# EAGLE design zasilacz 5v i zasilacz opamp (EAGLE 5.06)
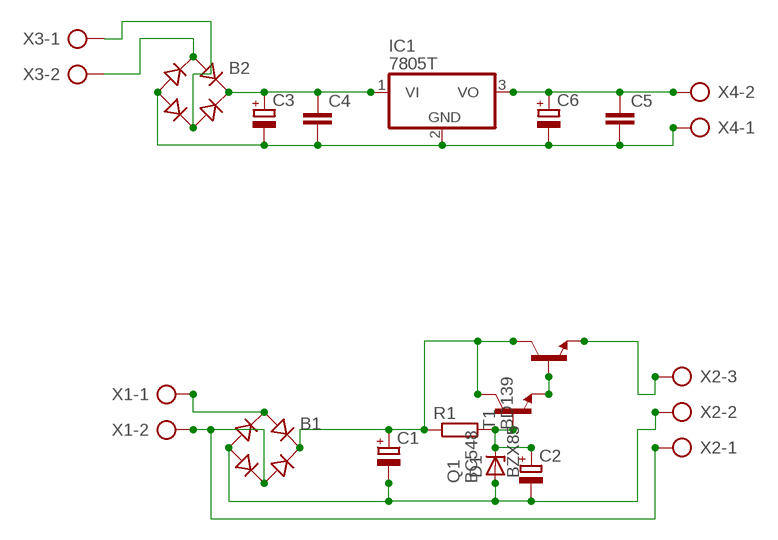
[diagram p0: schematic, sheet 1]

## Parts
B1  RB1A  [RB1A]
B2  RB1A  [RB1A]
C1  CPOL-EUE5-13  [E5-13]
C2  CPOL-EUE3.5-8  [E3,5-8]
C3  CPOL-EUE5-10.5  [E5-10,5]
C4  C-EU025-025X050  [C025-025X050]
C5  C-EU025-025X050  [C025-025X050]
C6  CPOL-EUE2.5-6  [E2,5-6]
D1  BZX85  [DO41Z10]
IC1  7805T  [TO220H]
Q1  BC548  [TO92-EBC]
R1  R-EU_0207/12  [0207/12]
T1  BD139  [TO126]
X1  AK300/2  [AK300/2]
X2  AK300/3  [AK300/3]
X3  AK500/2-H  [AK500/2-H]
X4  AK500/2-H  [AK500/2-H]

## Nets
N$2: B2.- C3.- C4.2 C5.2 C6.- IC1.2(GND) X4.1
N$3: B1.- C1.- C2.- D1.A X2.2
N$4: C2.+ D1.C Q1.B R1.2
N$5: B1.+ C1.+ Q1.C R1.1 T1.2(C)
N$6: Q1.E T1.3(B)
N$7: T1.1(E) X2.3
N$8: B1.AC2 X1.2 X2.1
N$9: B1.AC1 X1.1
N$11: B2.+ C3.+ C4.1 IC1.1(VI)
N$13: C5.1 C6.+ IC1.3(VO) X4.2
N$14: B2.AC2 X3.1
N$15: B2.AC1 X3.2

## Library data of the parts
B1 B2 = rectifier:RB1A: RECTIFIER 1 A
C1-C3 C6 = rcl:CPOL-EU: POLARIZED CAPACITOR, European symbol
C4 C5 = rcl:C-EU: CAPACITOR, European symbol
D1 = diode:BZX85: Z DIODE
IC1 = linear:78*: Positive VOLTAGE REGULATOR Source: http://cache.national.com/ds/LM/LM78L05.pdf http://www.fairchildsemi.com/ds/LM/LM7805.pdf
Q1 = transistor-npn:BC548*: NPN Transistor
R1 = rcl:R-EU_: RESISTOR, European symbol
T1 = transistor:BD139: NPN TRANSISTOR
X1 = con-ptr500:AK300/2: CONNECTOR
X2 = con-ptr500:AK300/3: CONNECTOR
X3 X4 = con-ptr500:AK500/2-H: CONNECTOR

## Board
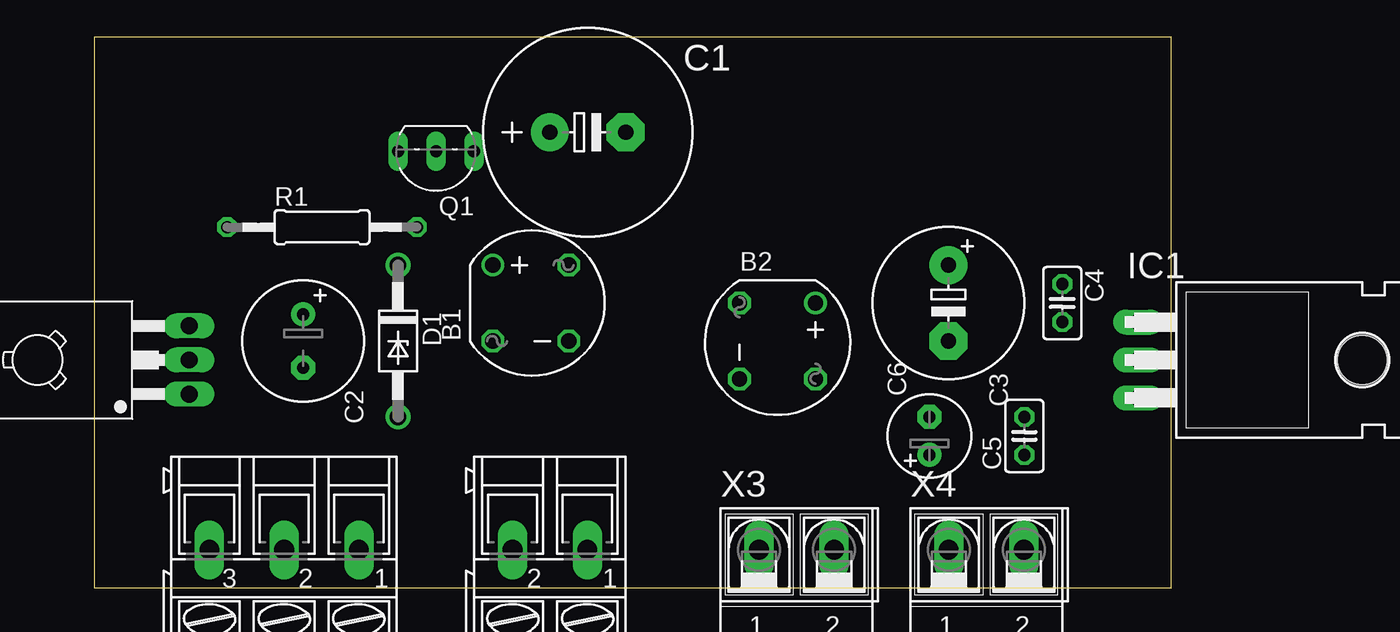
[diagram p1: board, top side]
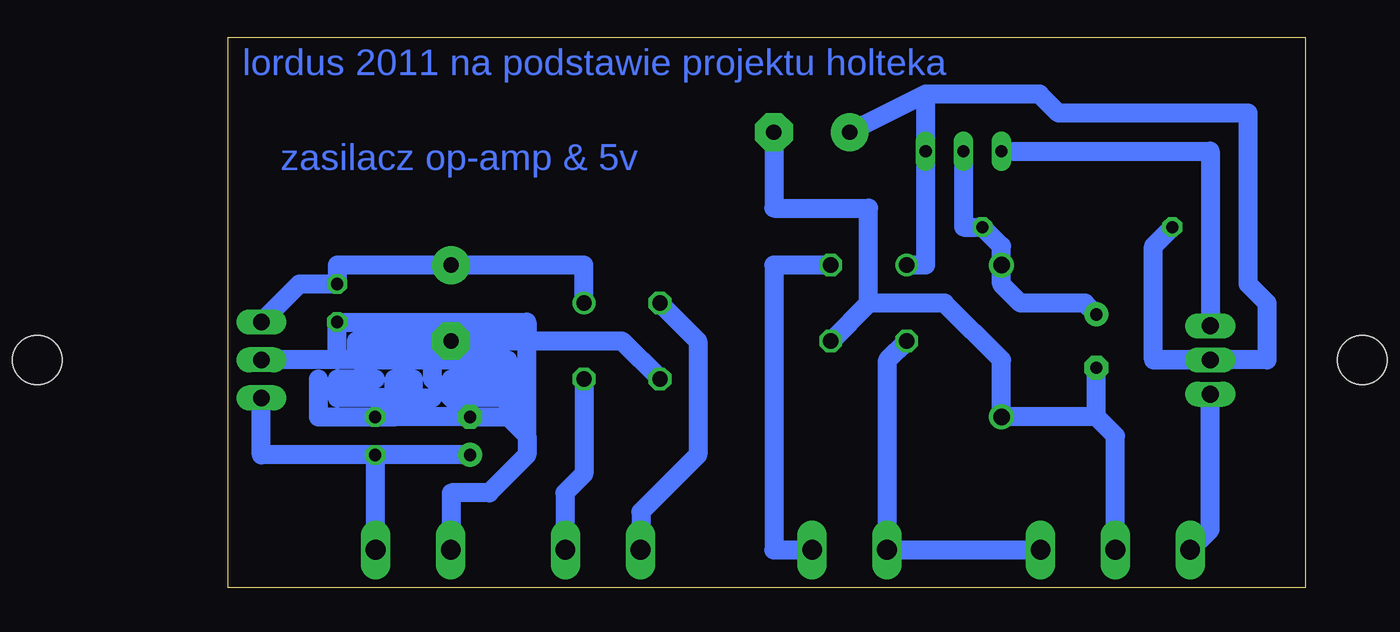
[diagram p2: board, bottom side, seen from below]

Size 72.06 x 36.82 mm. Coordinates in mm from the lower left corner, seen from the top.
Outline: 0,0 72.06,0 72.06,36.82 0,36.82 0,0
Copper layers (1*16): Top 0.035mm / dielectric 1.5mm / Bottom 0.035mm
Design rules "default": minimum track width 10mil, minimum drill 24mil, track to track 8mil, track to pad 8mil, pad to pad 8mil, via to via 8mil, smd to smd 8mil, copper to edge 40mil, drill to drill 8mil, minimum pad ring 10mil, minimum via ring 8mil, stop-mask expansion 4mil, vias tented up to drill 0mil, thermal gap 10mil

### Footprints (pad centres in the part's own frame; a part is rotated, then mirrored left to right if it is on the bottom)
RB1A = drill 1.016 round: + -2.54,2.54 | drill 1.016 octagon: - 2.54,-2.54; AC1 2.54,2.54; AC2 -2.54,-2.54
E5-13 = drill 1.016 pad 2.54 round: + -2.54,0 | drill 1.016 pad 2.54 octagon: - 2.54,0
E3,5-8 = drill 0.813 pad 1.6 round: + -1.778,0 | drill 0.813 pad 1.6 octagon: - 1.778,0
E5-10,5 = drill 1.016 pad 2.54 round: + -2.54,0 | drill 1.016 pad 2.54 octagon: - 2.54,0
C025-025X050 = drill 0.813 octagon: 1 -1.27,0; 2 1.27,0
E2,5-6 = drill 0.813 pad 1.6 round: + -1.27,0 | drill 0.813 pad 1.6 octagon: - 1.27,0
DO41Z10 = drill 1.118 round: A 5.08,0; C -5.08,0
TO220H = drill 1.118 long: 1 -2.54,-10.16; 2 0,-10.16; 3 2.54,-10.16 | hole 3.302: 0,4.826
TO92-EBC = drill 0.813 long: B 0,-1.27; C -2.54,-1.27; E 2.54,-1.27
0207/12 = drill 0.813 octagon: 1 -6.35,0; 2 6.35,0
TO126 = drill 1.118 long: 1 -2.286,-5.08; 2 0,-5.08; 3 2.286,-5.08 | hole 3.302: 0,5.08
AK300/2 = drill 1.321 long: 1 -2.515,0; 2 2.489,0
AK300/3 = drill 1.321 long: 1 -5.004,0; 2 0,0; 3 5.004,0
AK500/2-H = drill 1.321 long: 1 -2.515,0; 2 2.515,0

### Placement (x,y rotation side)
B1  29.21,19.05 0 top
B2  45.72,16.51 270 top
C1  33.02,30.48 0 top
C2  13.97,16.51 270 top
C3  57.15,19.05 270 top
C4  64.77,19.05 270 top
C5  62.23,10.16 90 top
C6  55.88,10.16 90 top
D1  20.32,16.51 270 top
IC1  80.01,15.24 270 top
Q1  22.86,27.94 180 top
R1  15.24,24.13 0 top
T1  1.27,15.24 90 top
X1  30.48,2.54 180 top
X2  12.7,2.54 180 top
X3  46.99,2.54 0 top
X4  59.69,2.54 0 top

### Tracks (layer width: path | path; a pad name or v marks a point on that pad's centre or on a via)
N$2
  Bottom 1.27: 66.04,13.97 66.04,11.43 60.96,11.43 | 52.07,16.51 45.72,16.51 B2.- | 52.07,16.51 C3.- 58.42,15.24 | 64.77,15.24 C4.2 52.07,17.78 52.07,16.51 | 64.77,15.24 IC1.2 | 58.42,15.24 63.5,15.24 | 63.5,15.24 64.77,15.24 | 58.42,15.24 58.42,13.97 C6.- | C6.- 60.96,11.43 | 60.96,11.43 C5.2 | C6.- 53.34,11.43 | 53.34,11.43 52.07,10.16 | 52.07,10.16 52.07,8.89 54.61,6.35 57.15,6.35 57.15,2.56 X4.1 | 60.96,11.43 60.96,13.97 59.69,13.97 59.69,12.7 | 59.69,12.7 58.42,12.7 | 59.69,12.7 64.77,12.7 64.77,13.97 62.23,13.97 | 52.07,10.16 52.07,13.97 | 52.07,13.97 52.07,16.51 | 52.07,16.51 63.5,16.51 63.5,15.24 | 63.5,15.24 53.34,15.24 53.34,12.7 57.15,12.7 57.15,13.97 53.34,13.97 53.34,11.43 | 53.34,11.43 52.07,11.43 52.07,13.97
N$3
  Bottom 1.27: 13.97,11.43 D1.A 20.32,15.24 24.13,19.05 29.21,19.05 | 13.97,11.43 C2.- | 13.97,11.43 12.7,10.16 X2.2 | 29.21,19.05 B1.- | 29.21,19.05 29.21,25.4 35.56,25.4 C1.-
N$4
  Bottom 1.27: C2.+ 14.73,19.05 19.05,19.05 20.32,20.32 D1.C 20.32,22.86 R1.2 22.86,24.13 Q1.B
N$5
  Bottom 1.27: 10.16,15.24 T1.2 | B1.+ 25.4,21.59 Q1.C 25.4,33.02 | R1.1 10.16,22.86 10.16,15.24 | 10.16,15.24 2.54,15.24 2.54,19.05 3.81,20.32 3.81,31.75 16.51,31.75 17.78,33.02 25.4,33.02 | 25.4,33.02 C1.+
N$6
  Bottom 1.27: Q1.E 6.35,29.21 T1.3
N$7
  Bottom 1.27: 7.62,2.54 X2.3 6.35,3.89 T1.1
N$8
  Bottom 1.27: B1.AC2 27.94,15.24 27.94,2.59 X1.2 X2.1
N$9
  Bottom 1.27: B1.AC1 35.56,21.59 35.56,2.54 X1.1
N$11
  Bottom 1.27: B2.+ 48.26,21.59 C3.+ 64.77,21.59 C4.1 67.31,20.32 IC1.1
N$13
  Bottom 1.27: C5.1 62.23,2.56 X4.2 | C6.+ C5.1 | C5.1 69.85,8.89 IC1.3
N$14
  Bottom 1.27: B2.AC2 40.64,16.51 40.64,8.89 44.45,5.08 44.45,2.56 X3.1
N$15
  Bottom 1.27: B2.AC1 48.26,7.62 49.53,6.35 49.53,2.56 X3.2

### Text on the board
Bottom: lordus 2011 na podstawie projektu holteka | zasilacz op-amp & 5v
